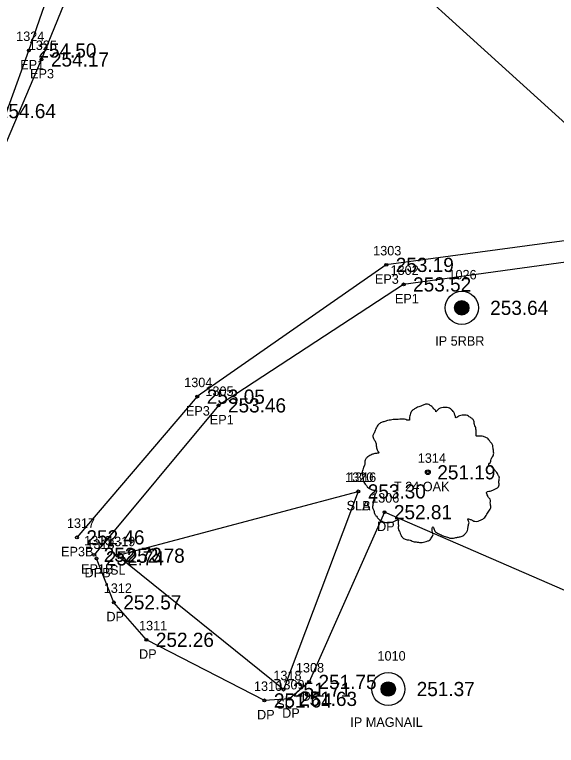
# Model space of a CAD drawing. Extents: x 1961231 to 1962574, y 799865 to 801120.
# Drawn here: x 1962009.5 to 1962066.8, y 800391.4 to 800468.6 of the extents above; entities that cross this region are included whole.
import ezdxf

# ---------------------------------------------------------------- set-up
doc = ezdxf.new("R2010")
doc.units = 0
for name, color, linetype in [('RD_EX_Driveway', 7, 'Continuous'), ('RD_EX_Driveway_txCode', 7, 'Continuous'), ('RD_EX_DV_Prop_txCode', 7, 'Continuous'), ('RD_EX_DV_PropPin', 7, 'Continuous'), ('RD_EX_Road', 7, 'Continuous'), ('RD_EX_Road_txCode', 7, 'Continuous'), ('RD_EX_TX_Driveway_ELEV', 7, 'Continuous'), ('RD_EX_TX_DV_Prop_ELEV', 7, 'Continuous'), ('RD_EX_TX_Road_ELEV', 7, 'Continuous'), ('RD_EX_TX_UT_ELEV', 7, 'Continuous'), ('RD_EX_TX_VEG_ELEV', 7, 'Continuous'), ('RD_EX_VEG', 7, 'Continuous'), ('RD_EX_VEG_txCode', 7, 'Continuous'), ('RD_SMD_Locator', 7, 'Continuous')]:
    doc.layers.add(name, color=color, linetype=linetype)

msp = doc.modelspace()

# ---------------------------------------------------------------- linework, layer by layer
at = {"layer": 'RD_EX_Driveway'}
msp.add_lwpolyline([(1962116.507, 800348.313), (1962122.25, 800360.246), (1962116.96, 800363.772), (1962115.285, 800366.298), (1962115.229, 800369.61), (1962121.598, 800384.345), (1962097.146, 800394.939), (1962048.583, 800416.046), (1962040.612, 800398.112), (1962038.55, 800396.322), (1962035.897, 800396.16), (1962023.426, 800402.56), (1962019.983, 800406.516), (1962018.146, 800411.163)], dxfattribs=at)
at = {"layer": 'RD_EX_DV_PropPin'}
for p, q in [((1962056.369, 800436.973), (1962056.369, 800438.286)), ((1962056.404, 800436.954), (1962056.404, 800438.305)), ((1962056.439, 800436.936), (1962056.439, 800438.322)), ((1962056.474, 800436.922), (1962056.474, 800438.337)), ((1962056.509, 800436.909), (1962056.509, 800438.35)), ((1962056.544, 800436.898), (1962056.544, 800438.361)), ((1962056.579, 800436.889), (1962056.579, 800438.37)), ((1962056.614, 800436.881), (1962056.614, 800438.377)), ((1962056.649, 800436.875), (1962056.649, 800438.383)), ((1962056.684, 800436.871), (1962056.684, 800438.387)), ((1962056.719, 800436.869), (1962056.719, 800438.389)), ((1962056.754, 800436.868), (1962056.754, 800438.39)), ((1962056.789, 800436.869), (1962056.789, 800438.389)), ((1962056.825, 800436.871), (1962056.825, 800438.387)), ((1962056.86, 800436.875), (1962056.86, 800438.383)), ((1962056.895, 800436.881), (1962056.895, 800438.377)), ((1962056.93, 800436.889), (1962056.93, 800438.37)), ((1962056.965, 800436.898), (1962056.965, 800438.361)), ((1962057, 800436.909), (1962057, 800438.35)), ((1962057.035, 800436.922), (1962057.035, 800438.337)), ((1962057.07, 800436.936), (1962057.07, 800438.322)), ((1962057.105, 800436.954), (1962057.105, 800438.305)), ((1962057.14, 800436.973), (1962057.14, 800438.286)), ((1962056.019, 800437.433), (1962056.019, 800437.825)), ((1962056.054, 800437.331), (1962056.054, 800437.927)), ((1962056.089, 800437.26), (1962056.089, 800437.999)), ((1962056.124, 800437.203), (1962056.124, 800438.056)), ((1962056.159, 800437.155), (1962056.159, 800438.103)), ((1962056.194, 800437.114), (1962056.194, 800438.144)), ((1962056.229, 800437.078), (1962056.229, 800438.18)), ((1962056.264, 800437.047), (1962056.264, 800438.211)), ((1962056.299, 800437.019), (1962056.299, 800438.239)), ((1962056.334, 800436.995), (1962056.334, 800438.264)), ((1962057.175, 800436.995), (1962057.175, 800438.264)), ((1962057.21, 800437.019), (1962057.21, 800438.239)), ((1962057.245, 800437.047), (1962057.245, 800438.211)), ((1962057.28, 800437.078), (1962057.28, 800438.18)), ((1962057.315, 800437.114), (1962057.315, 800438.144)), ((1962057.35, 800437.155), (1962057.35, 800438.103)), ((1962057.385, 800437.203), (1962057.385, 800438.056)), ((1962057.42, 800437.26), (1962057.42, 800437.999)), ((1962057.455, 800437.331), (1962057.455, 800437.927)), ((1962057.49, 800437.433), (1962057.49, 800437.825)), ((1962048.253, 800397.167), (1962048.253, 800397.56)), ((1962048.288, 800397.066), (1962048.288, 800397.661)), ((1962048.323, 800396.994), (1962048.323, 800397.733)), ((1962048.358, 800396.937), (1962048.358, 800397.79)), ((1962048.393, 800396.889), (1962048.393, 800397.838)), ((1962048.428, 800396.848), (1962048.428, 800397.879)), ((1962048.463, 800396.813), (1962048.463, 800397.914)), ((1962048.498, 800396.781), (1962048.498, 800397.946)), ((1962048.533, 800396.754), (1962048.533, 800397.973)), ((1962048.568, 800396.729), (1962048.568, 800397.998)), ((1962048.603, 800396.707), (1962048.603, 800398.02)), ((1962048.638, 800396.688), (1962048.638, 800398.039)), ((1962048.673, 800396.671), (1962048.673, 800398.056)), ((1962048.708, 800396.656), (1962048.708, 800398.071)), ((1962048.743, 800396.643), (1962048.743, 800398.084)), ((1962048.778, 800396.632), (1962048.778, 800398.095)), ((1962048.813, 800396.623), (1962048.813, 800398.104)), ((1962048.848, 800396.615), (1962048.848, 800398.112)), ((1962048.883, 800396.61), (1962048.883, 800398.117)), ((1962048.918, 800396.606), (1962048.918, 800398.121)), ((1962048.953, 800396.603), (1962048.953, 800398.124)), ((1962048.988, 800396.602), (1962048.988, 800398.125)), ((1962049.023, 800396.603), (1962049.023, 800398.124)), ((1962049.058, 800396.606), (1962049.058, 800398.121)), ((1962049.093, 800396.61), (1962049.093, 800398.117)), ((1962049.128, 800396.615), (1962049.128, 800398.112)), ((1962049.163, 800396.623), (1962049.163, 800398.104)), ((1962049.198, 800396.632), (1962049.198, 800398.095)), ((1962049.233, 800396.643), (1962049.233, 800398.084)), ((1962049.268, 800396.656), (1962049.268, 800398.071)), ((1962049.303, 800396.671), (1962049.303, 800398.056)), ((1962049.338, 800396.688), (1962049.338, 800398.039)), ((1962049.373, 800396.707), (1962049.373, 800398.02)), ((1962049.408, 800396.729), (1962049.408, 800397.998)), ((1962049.443, 800396.754), (1962049.443, 800397.973)), ((1962049.478, 800396.781), (1962049.478, 800397.946)), ((1962049.513, 800396.813), (1962049.513, 800397.914)), ((1962049.548, 800396.848), (1962049.548, 800397.879)), ((1962049.583, 800396.889), (1962049.583, 800397.838)), ((1962049.618, 800396.937), (1962049.618, 800397.79)), ((1962049.653, 800396.994), (1962049.653, 800397.733)), ((1962049.688, 800397.066), (1962049.688, 800397.661)), ((1962049.723, 800397.167), (1962049.723, 800397.56))]:
    msp.add_line(p, q, dxfattribs=at)
for centre, radius in [((1962056.754, 800437.629), 1.75), ((1962056.754, 800437.629), 0.761), ((1962048.988, 800397.363), 1.75), ((1962048.988, 800397.363), 0.761)]:
    msp.add_circle(centre, radius, dxfattribs=at)
at = {"layer": 'RD_EX_Road'}
for points in [[(1962241.795, 800315.68), (1962238.351, 800317.597), (1962189.917, 800352.695), (1962151.637, 800383.489), (1962113.782, 800416.386), (1962074.109, 800451.288), (1962034.784, 800486.956), (1962017.07, 800503.174), (1961999.461, 800519.248), (1961962.476, 800552.117), (1961937.077, 800573.106), (1961923.189, 800584.904), (1961883.072, 800617.432), (1961838.294, 800653.432), (1961801.423, 800682.572), (1961728.409, 800740.856), (1961722.948, 800745.107), (1961689.132, 800771.929)], [(1961992.53, 800418.336), (1962000.944, 800437), (1962011.011, 800464.808), (1962016.837, 800481.64), (1962015.313, 800499.647), (1961996.985, 800516.713), (1961979.472, 800530.761), (1961969.799, 800538.748), (1961958.277, 800547.161), (1961941.067, 800560.824), (1961925.414, 800573.413), (1961918.19, 800579.247), (1961879.318, 800611.179), (1961866.074, 800621.075), (1961838.294, 800653.432)], [(1962000.944, 800437), (1962012.341, 800463.86), (1962019.243, 800480.795), (1962017.644, 800497.353), (1962015.313, 800499.647)], [(1962080.072, 800442.592), (1962072.307, 800445.338), (1962048.775, 800442.163), (1962028.807, 800428.248), (1962016.088, 800413.382)], [(1962238.351, 800317.597), (1962235.932, 800316.569), (1962188.31, 800350.578), (1962150.215, 800381.436), (1962111.822, 800414.885), (1962080.072, 800442.592), (1962070.813, 800442.862), (1962050.611, 800440.1), (1962031.046, 800427.323), (1962017.916, 800411.541)]]:
    msp.add_lwpolyline(points, dxfattribs=at)
at = {"layer": 'RD_EX_VEG'}
msp.add_lwpolyline([(1962045.819, 800418.235), (1962037.907, 800397.296), (1962020.342, 800411.45), (1962045.819, 800418.235)], dxfattribs=at)
for centre, radius in [((1962053.167, 800420.256), 0.25), ((1962053.155, 800420.237), 0.0001)]:
    msp.add_circle(centre, radius, dxfattribs=at)
for points in [[(1962053.299, 800427.424), (1962052.999, 800427.449), (1962052.675, 800427.349), (1962052.425, 800427.249), (1962052.2, 800427.174), (1962051.975, 800427.074), (1962051.675, 800426.899), (1962051.45, 800426.699), (1962051.325, 800426.449), (1962051.275, 800426.224), (1962051.225, 800425.949), (1962051.225, 800425.774), (1962051.1, 800425.749), (1962050.95, 800425.774), (1962050.7, 800425.849), (1962050.451, 800425.849), (1962050.201, 800425.849), (1962049.851, 800425.824), (1962049.501, 800425.824), (1962049.226, 800425.774), (1962048.901, 800425.724), (1962048.526, 800425.599), (1962048.177, 800425.474), (1962047.877, 800425.224), (1962047.627, 800424.75), (1962047.502, 800424.4), (1962047.352, 800424.15), (1962047.502, 800423.7), (1962047.677, 800423.35), (1962047.702, 800423.15), (1962047.777, 800422.726), (1962047.877, 800422.501), (1962048.002, 800422.301), (1962047.927, 800422.276), (1962047.552, 800422.226), (1962047.252, 800422.126), (1962046.827, 800421.901), (1962046.602, 800421.676), (1962046.502, 800421.351), (1962046.477, 800421.001), (1962046.377, 800420.801), (1962046.302, 800420.527), (1962046.277, 800420.452), (1962046.227, 800420.127), (1962046.327, 800419.677), (1962046.352, 800419.327), (1962046.477, 800419.102), (1962046.627, 800418.927), (1962046.802, 800418.677), (1962047.202, 800418.452), (1962047.527, 800418.352), (1962047.727, 800418.328), (1962047.552, 800417.828), (1962047.502, 800417.478), (1962047.377, 800417.078), (1962047.377, 800417.003), (1962047.327, 800416.528), (1962047.477, 800416.203), (1962047.552, 800415.829), (1962047.727, 800415.604), (1962048.002, 800415.304), (1962048.326, 800415.079), (1962048.826, 800414.954), (1962049.226, 800414.979), (1962049.801, 800415.154), (1962050.051, 800415.229), (1962050.026, 800415.054), (1962050.051, 800414.679), (1962050.051, 800414.254), (1962050.201, 800413.929), (1962050.301, 800413.655), (1962050.451, 800413.405), (1962050.775, 800413.18), (1962051.175, 800413.105), (1962051.6, 800412.955), (1962052.05, 800412.88), (1962052.55, 800412.855), (1962053.149, 800413.005), (1962053.424, 800413.13), (1962053.524, 800413.305), (1962053.724, 800413.68), (1962053.674, 800413.904), (1962053.699, 800414.504), (1962053.799, 800414.329), (1962053.974, 800413.979), (1962054.474, 800413.68), (1962054.874, 800413.505), (1962055.348, 800413.355), (1962055.648, 800413.28), (1962056.123, 800413.355), (1962056.498, 800413.43), (1962056.873, 800413.555), (1962057.173, 800413.829), (1962057.348, 800414.104), (1962057.398, 800414.379), (1962057.472, 800414.754), (1962057.522, 800414.929)], [(1962057.522, 800414.929), (1962057.448, 800415.104), (1962057.398, 800415.354), (1962057.472, 800415.329), (1962057.647, 800415.279), (1962057.922, 800415.154), (1962058.147, 800415.079), (1962058.472, 800415.104), (1962058.747, 800415.204), (1962059.197, 800415.479), (1962059.472, 800415.954), (1962059.746, 800416.353), (1962059.821, 800416.678), (1962059.771, 800416.903), (1962059.746, 800417.403), (1962059.547, 800417.653), (1962059.497, 800417.778), (1962059.397, 800418.178), (1962059.472, 800418.228), (1962059.746, 800418.278), (1962060.121, 800418.402), (1962060.396, 800418.527), (1962060.621, 800418.702), (1962060.696, 800418.927), (1962060.671, 800419.327), (1962060.721, 800419.727), (1962060.646, 800419.877), (1962060.546, 800420.027), (1962060.471, 800420.227), (1962060.321, 800420.377), (1962060.221, 800420.527), (1962060.121, 800420.626), (1962059.996, 800420.776), (1962059.821, 800420.901), (1962059.672, 800420.951), (1962059.622, 800421.101), (1962059.771, 800421.301), (1962059.821, 800421.401), (1962059.846, 800421.626), (1962060.071, 800421.976), (1962060.121, 800422.376), (1962060.071, 800422.801), (1962060.021, 800423.075), (1962059.871, 800423.35), (1962059.672, 800423.6), (1962059.547, 800423.775), (1962059.372, 800423.9), (1962059.047, 800424.025), (1962058.797, 800424.075), (1962058.447, 800424.075), (1962058.247, 800424.125), (1962058.272, 800424.175), (1962058.272, 800424.325), (1962058.272, 800424.6), (1962058.197, 800425.05), (1962058.047, 800425.549), (1962058.047, 800425.574), (1962057.947, 800425.824), (1962057.722, 800426.024), (1962057.547, 800426.124), (1962057.348, 800426.249), (1962057.098, 800426.274), (1962056.798, 800426.274), (1962056.523, 800426.224), (1962056.323, 800426.124), (1962056.148, 800425.999), (1962056.073, 800426.149), (1962055.973, 800426.449), (1962055.923, 800426.599), (1962055.773, 800426.774), (1962055.548, 800426.974), (1962055.098, 800427.099), (1962054.474, 800427.024), (1962054.174, 800426.824), (1962054.024, 800426.649), (1962053.974, 800426.774), (1962053.774, 800426.974), (1962053.674, 800427.149), (1962053.499, 800427.274), (1962053.349, 800427.374), (1962053.249, 800427.424)]]:
    msp.add_spline(points, degree=3, dxfattribs=at)
at = {"layer": 'RD_SMD_Locator'}
for centre in [(1962011.011, 800464.808), (1962012.341, 800463.86), (1962048.775, 800442.163), (1962050.611, 800440.1), (1962056.755, 800437.629), (1962028.807, 800428.248), (1962031.046, 800427.323), (1962053.167, 800420.256), (1962045.819, 800418.235), (1962045.819, 800418.235), (1962048.583, 800416.046), (1962016.088, 800413.382), (1962017.916, 800411.541), (1962018.146, 800411.163), (1962020.342, 800411.45), (1962019.983, 800406.516), (1962023.426, 800402.56), (1962040.612, 800398.112), (1962037.907, 800397.296), (1962048.988, 800397.363), (1962035.897, 800396.16), (1962038.55, 800396.322)]:
    msp.add_circle(centre, 0.15, dxfattribs=at)

# ---------------------------------------------------------------- texts
at = {"layer": 'RD_EX_Driveway_txCode'}
for s, p in [('1306', (1962047.173, 800417.046)), ('DP', (1962047.803, 800414.046)), ('1313', (1962017.083, 800412.163)), ('DPB', (1962016.894, 800409.163)), ('1312', (1962018.92, 800407.516)), ('DP', (1962019.203, 800404.516)), ('1311', (1962022.647, 800403.56)), ('DP', (1962022.647, 800400.56)), ('1308', (1962039.227, 800399.112)), ('1310', (1962034.795, 800397.16)), ('1309', (1962037.164, 800397.322)), ('DP', (1962039.833, 800396.112)), ('DP', (1962035.118, 800394.16)), ('DP', (1962037.771, 800394.322))]:
    msp.add_text(s, height=1, dxfattribs=at).set_placement(p)
at = {"layer": 'RD_EX_DV_Prop_txCode'}
for s, p in [('1026', (1962055.345, 800440.629)), ('IP 5RBR', (1962053.943, 800433.629)), ('1010', (1962047.846, 800400.364)), ('IP MAGNAIL', (1962044.972, 800393.364))]:
    msp.add_text(s, height=1, dxfattribs=at).set_placement(p)
at = {"layer": 'RD_EX_Road_txCode'}
for s, p in [('1324', (1962009.665, 800465.808)), ('1325', (1962010.994, 800464.86)), ('EP1', (1962010.09, 800462.808)), ('EP3', (1962011.136, 800461.86)), ('1303', (1962047.389, 800443.163)), ('1302', (1962049.226, 800441.1)), ('EP3', (1962047.57, 800440.163)), ('EP1', (1962049.69, 800438.1)), ('1304', (1962027.421, 800429.248)), ('1305', (1962029.66, 800428.323)), ('EP3', (1962027.602, 800426.248)), ('EP1', (1962030.125, 800425.323)), ('1317', (1962015.025, 800414.382)), ('1315', (1962016.853, 800412.541)), ('EP3B', (1962014.41, 800411.382)), ('EP1B', (1962016.522, 800409.541))]:
    msp.add_text(s, height=1, dxfattribs=at).set_placement(p)
at = {"layer": 'RD_EX_TX_Driveway_ELEV'}
for s, p in [('252.81', (1962049.583, 800415.296)), ('252.74', (1962019.146, 800410.413)), ('252.57', (1962020.983, 800405.766)), ('252.26', (1962024.426, 800401.81)), ('251.75', (1962041.612, 800397.362)), ('251.64', (1962036.897, 800395.41)), ('251.63', (1962039.55, 800395.572))]:
    msp.add_text(s, height=1.5, dxfattribs=at).set_placement(p)
at = {"layer": 'RD_EX_TX_DV_Prop_ELEV'}
for s, p in [('253.64', (1962059.755, 800436.879)), ('251.37', (1962051.988, 800396.614))]:
    msp.add_text(s, height=1.5, dxfattribs=at).set_placement(p)
at = {"layer": 'RD_EX_TX_Road_ELEV'}
for s, p in [('254.50', (1962012.011, 800464.058)), ('254.17', (1962013.341, 800463.11)), ('253.19', (1962049.775, 800441.413)), ('253.52', (1962051.611, 800439.35)), ('253.05', (1962029.807, 800427.498)), ('253.46', (1962032.046, 800426.573)), ('252.46', (1962017.088, 800412.632)), ('252.73', (1962018.916, 800410.791))]:
    msp.add_text(s, height=1.5, dxfattribs=at).set_placement(p)
at = {"layer": 'RD_EX_TX_UT_ELEV'}
msp.add_text('254.64', height=1.5, dxfattribs=at).set_placement((1962007.733, 800457.661))
at = {"layer": 'RD_EX_TX_VEG_ELEV'}
for s, p in [('251.19', (1962054.167, 800419.506)), ('253.30', (1962046.819, 800417.485)), ('253.30', (1962046.819, 800417.485)), ('252.78', (1962021.342, 800410.7)), ('251.71', (1962038.907, 800396.546))]:
    msp.add_text(s, height=1.5, dxfattribs=at).set_placement(p)
at = {"layer": 'RD_EX_VEG_txCode'}
for s, p in [('1314', (1962052.104, 800421.256)), ('1320', (1962044.433, 800419.235)), ('1316', (1962044.732, 800419.235)), ('T 24 OAK', (1962049.585, 800418.256)), ('SLA', (1962044.574, 800416.235)), ('SLB', (1962044.59, 800416.235)), ('1319', (1962019.279, 800412.45)), ('SL', (1962019.586, 800409.45)), ('1318', (1962036.844, 800398.296)), ('SL', (1962037.151, 800395.296))]:
    msp.add_text(s, height=1, dxfattribs=at).set_placement(p)

doc.saveas('drawing.dxf')
